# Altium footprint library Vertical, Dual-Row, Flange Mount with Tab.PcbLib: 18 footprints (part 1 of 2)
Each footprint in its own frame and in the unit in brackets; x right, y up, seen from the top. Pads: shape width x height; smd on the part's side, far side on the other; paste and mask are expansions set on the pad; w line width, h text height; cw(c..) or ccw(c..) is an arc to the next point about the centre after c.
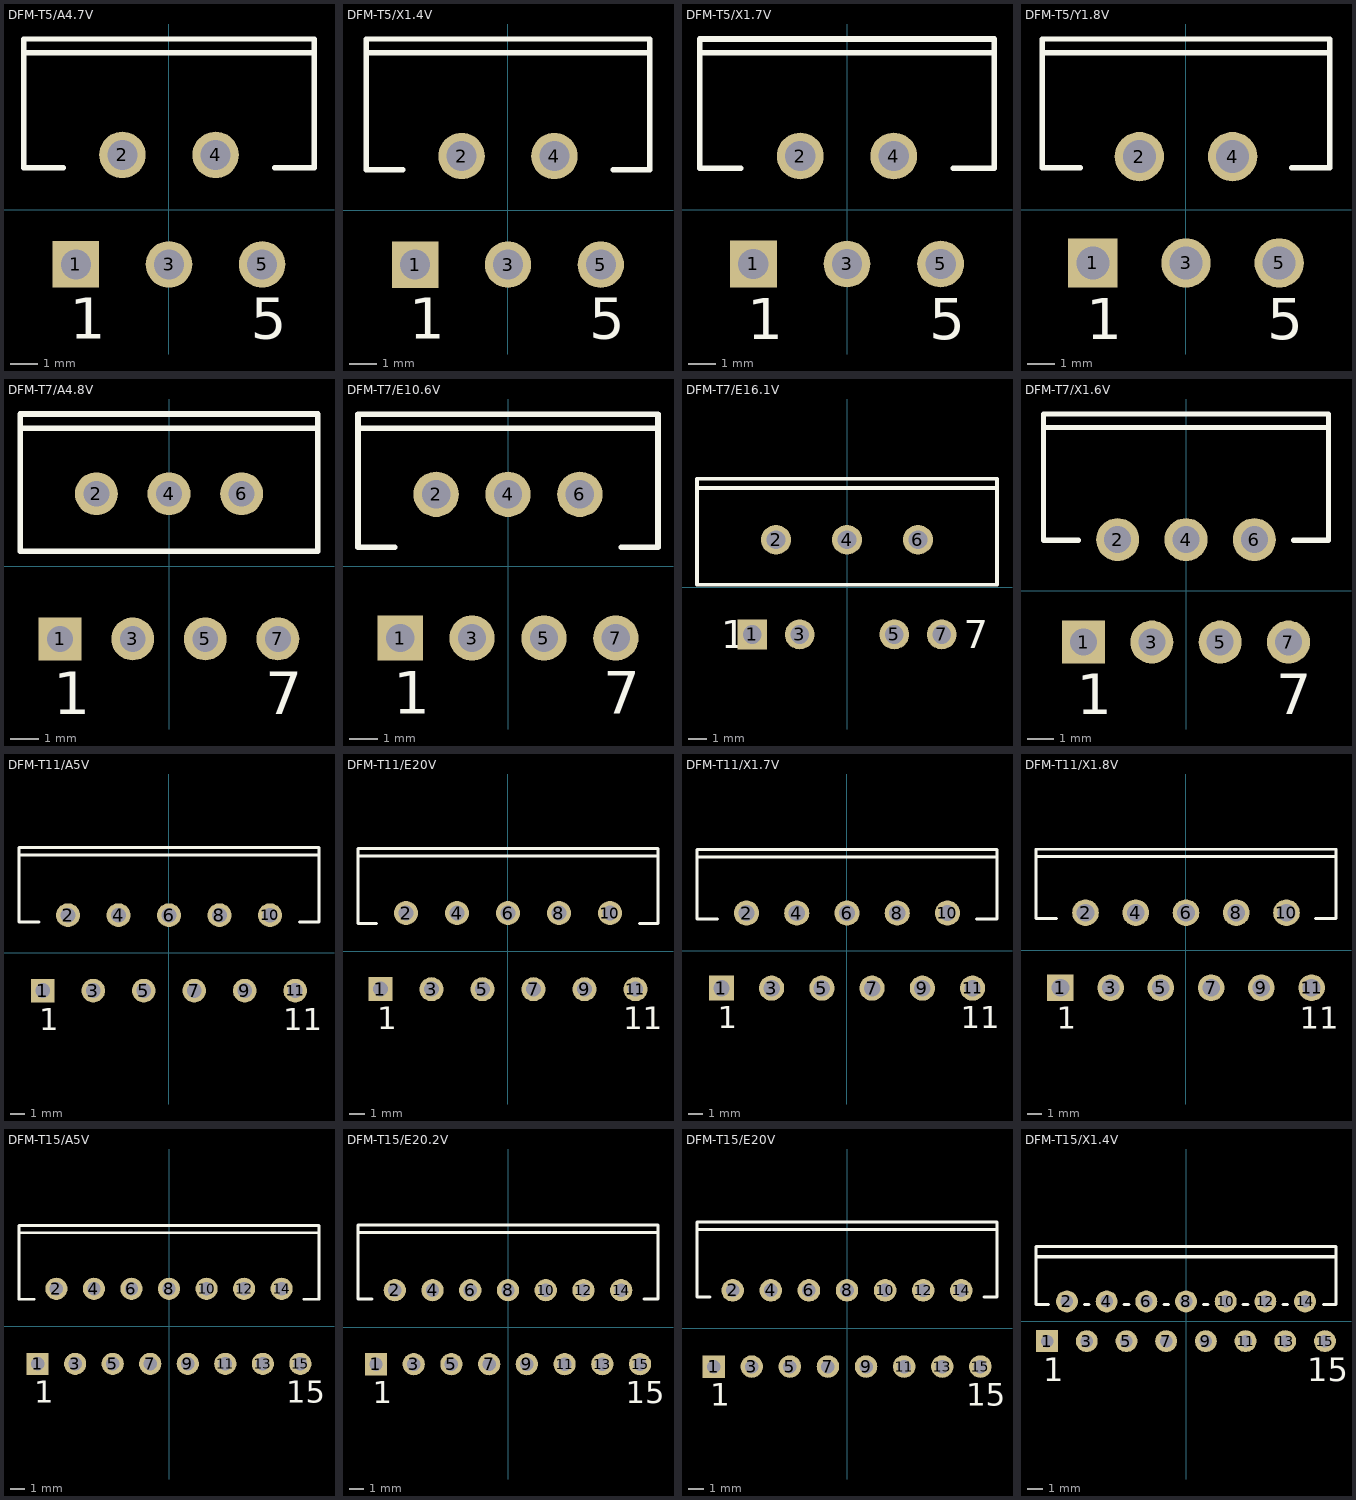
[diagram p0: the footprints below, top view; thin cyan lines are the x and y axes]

## DFM-T5/A4.7V [mm]
pads (5):
  rect 1.7x1.7 hole 1.1: 1(-3.4,-2)
  round 1.7 hole 1.1: 2(-1.7,2) 3(0,-2) 4(1.7,2) 5(3.4,-2)
Top Overlay:
  lines w0.2: -5.3,5.73 5.3,5.73 ; -3.854,1.53 -5.3,1.53 -5.3,6.23 5.3,6.23 5.3,1.53 3.854,1.53
  text "5" at 2.98,-4.725 h1.5
  text "1" at -3.62,-4.725 h1.5

## DFM-T5/X1.4V [mm]
pads (5):
  rect 1.7x1.7 hole 1.1: 1(-3.4,-1.99)
  round 1.7 hole 1.1: 2(-1.7,1.99) 3(0,-1.99) 4(1.7,1.99) 5(3.4,-1.99)
Top Overlay:
  lines w0.2: -5.2,5.78 5.2,5.78 ; -3.854,1.48 -5.2,1.48 -5.2,6.28 5.2,6.28 5.2,1.48 3.854,1.48
  text "1" at -3.62,-4.715 h1.5
  text "5" at 2.98,-4.715 h1.5

## DFM-T5/X1.7V [mm]
pads (5):
  rect 1.7x1.7 hole 1.1: 1(-3.4,-1.96)
  round 1.7 hole 1.1: 2(-1.7,1.96) 3(0,-1.96) 4(1.7,1.96) 5(3.4,-1.96)
Top Overlay:
  lines w0.2: -5.35,5.71 5.35,5.71 ; -3.854,1.51 -5.35,1.51 -5.35,6.21 5.35,6.21 5.35,1.51 3.854,1.51
  text "5" at 2.98,-4.685 h1.5
  text "1" at -3.62,-4.685 h1.5

## DFM-T5/Y1.8V [mm]
pads (5):
  rect 1.8x1.8 hole 1.2: 1(-3.4,-1.94)
  round 1.8 hole 1.2: 2(-1.7,1.94) 3(0,-1.94) 4(1.7,1.94) 5(3.4,-1.94)
Top Overlay:
  lines w0.2: -5.25,5.73 5.25,5.73 ; -3.854,1.53 -5.25,1.53 -5.25,6.23 5.25,6.23 5.25,1.53 3.854,1.53
  text "1" at -3.64,-4.715 h1.5
  text "5" at 2.96,-4.715 h1.5

## DFM-T7/A4.8V [mm]
pads (7):
  rect 1.5x1.5 hole 0.9: 1(-3.81,-2.54)
  round 1.5 hole 0.9: 2(-2.54,2.54) 3(-1.27,-2.54) 4(0,2.54) 5(1.27,-2.54) 6(2.54,2.54) 7(3.81,-2.54)
Top Overlay:
  lines w0.2: -5.2,4.83 5.2,4.83 ; -5.2,0.53 -5.2,5.33 5.2,5.33 5.2,0.53 -5.2,0.53
  text "1" at -4.05,-5.165 h1.5
  text "7" at 3.37,-5.165 h1.5

## DFM-T7/E10.6V [mm]
pads (7):
  rect 1.6x1.6 hole 1: 1(-3.81,-2.54)
  round 1.6 hole 1: 2(-2.54,2.54) 3(-1.27,-2.54) 4(0,2.54) 5(1.27,-2.54) 6(2.54,2.54) 7(3.81,-2.54)
Top Overlay:
  lines w0.2: -5.3,4.87 5.3,4.87 ; -4,0.67 -5.3,0.67 -5.3,5.37 5.3,5.37 5.3,0.67 4,0.67
  text "1" at -4.06,-5.215 h1.5
  text "7" at 3.36,-5.215 h1.5

## DFM-T7/E16.1V [mm]
pads (7):
  rect 1.6x1.6 hole 1: 1(-5.08,-2.54)
  round 1.6 hole 1: 2(-3.81,2.54) 3(-2.54,-2.54) 4(0,2.54) 5(2.54,-2.54) 6(3.81,2.54) 7(5.08,-2.54)
Top Overlay:
  lines w0.2: -8.05,5.32 8.05,5.32 ; -8.05,0.12 8.05,0.12 8.05,5.82 -8.05,5.82 -8.05,0.12
  text "7" at 6.255,-3.29 h1.5
  text "1" at -6.755,-3.29 h1.5

## DFM-T7/X1.6V [mm]
pads (7):
  rect 1.6x1.6 hole 1: 1(-3.81,-1.905)
  round 1.6 hole 1: 2(-2.54,1.905) 3(-1.27,-1.905) 4(0,1.905) 5(1.27,-1.905) 6(2.54,1.905) 7(3.81,-1.905)
Top Overlay:
  lines w0.2: -5.3,6.075 5.3,6.075 ; -4,1.875 -5.3,1.875 -5.3,6.575 5.3,6.575 5.3,1.875 4,1.875
  text "1" at -4.06,-4.58 h1.5
  text "7" at 3.36,-4.58 h1.5

## DFM-T11/A5V [mm]
pads (11):
  rect 1.6x1.6 hole 1: 1(-8.5,-2.54)
  round 1.6 hole 1: 2(-6.8,2.54) 3(-5.1,-2.54) 4(-3.4,2.54) 5(-1.7,-2.54) 6(0,2.54) 7(1.7,-2.54) 8(3.4,2.54) 9(5.1,-2.54) 10(6.8,2.54) 11(8.5,-2.54)
Top Overlay:
  lines w0.2: -10.1,6.59 10.1,6.59 ; -8.754,2.09 -10.1,2.09 -10.1,7.09 10.1,7.09 10.1,2.09 8.774,2.09
  text "11" at 7.69,-5.215 h1.5
  text "1" at -8.73,-5.215 h1.5

## DFM-T11/E20V [mm]
pads (11):
  rect 1.6x1.6 hole 1: 1(-8.5,-2.54)
  round 1.6 hole 1: 2(-6.8,2.54) 3(-5.1,-2.54) 4(-3.4,2.54) 5(-1.7,-2.54) 6(0,2.54) 7(1.7,-2.54) 8(3.4,2.54) 9(5.1,-2.54) 10(6.8,2.54) 11(8.5,-2.54)
Top Overlay:
  lines w0.2: -10,6.33 9.9,6.33 ; -8.754,1.83 -10,1.83 -10,6.83 10,6.83 10,1.83 8.774,1.83
  text "1" at -8.73,-5.215 h1.5
  text "11" at 7.67,-5.215 h1.5

## DFM-T11/X1.7V [mm]
pads (11):
  rect 1.7x1.7 hole 1.1: 1(-8.5,-2.54)
  round 1.7 hole 1.1: 2(-6.8,2.54) 3(-5.1,-2.54) 4(-3.4,2.54) 5(-1.7,-2.54) 6(0,2.54) 7(1.7,-2.54) 8(3.4,2.54) 9(5.1,-2.54) 10(6.8,2.54) 11(8.5,-2.54)
Top Overlay:
  lines w0.2: -10.15,6.34 10.15,6.34 ; -8.754,2.14 -10.15,2.14 -10.15,6.84 10.15,6.84 10.15,2.14 8.774,2.14
  text "11" at 7.71,-5.265 h1.5
  text "1" at -8.74,-5.265 h1.5

## DFM-T11/X1.8V [mm]
pads (11):
  rect 1.8x1.8 hole 1.2: 1(-8.5,-2.54)
  round 1.8 hole 1.2: 2(-6.8,2.54) 3(-5.1,-2.54) 4(-3.4,2.54) 5(-1.7,-2.54) 6(0,2.54) 7(1.7,-2.54) 8(3.4,2.54) 9(5.1,-2.54) 10(6.8,2.54) 11(8.5,-2.54)
Top Overlay:
  lines w0.2: -10.15,6.33 10.15,6.33 ; -8.754,2.13 -10.15,2.13 -10.15,6.83 10.15,6.83 10.15,2.13 8.774,2.13
  text "11" at 7.71,-5.315 h1.5
  text "1" at -8.74,-5.315 h1.5

## DFM-T15/A5V [mm]
pads (15):
  rect 1.5x1.5 hole 0.9: 1(-8.89,-2.54)
  round 1.5 hole 0.9: 2(-7.62,2.54) 3(-6.35,-2.54) 4(-5.08,2.54) 5(-3.81,-2.54) 6(-2.54,2.54) 7(-1.27,-2.54) 8(0,2.54) 9(1.27,-2.54) 10(2.54,2.54) 11(3.81,-2.54) 12(5.08,2.54) 13(6.35,-2.54) 14(7.62,2.54) 15(8.89,-2.54)
Top Overlay:
  lines w0.2: -10.15,6.33 10.05,6.33 ; -9.144,1.83 -10.15,1.83 -10.15,6.83 10.15,6.83 10.15,1.83 9.144,1.83
  text "1" at -9.12,-5.165 h1.5
  text "15" at 7.95,-5.165 h1.5

## DFM-T15/E20.2V [mm]
pads (15):
  rect 1.5x1.5 hole 0.9: 1(-8.89,-2.49)
  round 1.5 hole 0.9: 2(-7.62,2.49) 3(-6.35,-2.49) 4(-5.08,2.49) 5(-3.81,-2.49) 6(-2.54,2.49) 7(-1.27,-2.49) 8(0,2.49) 9(1.27,-2.49) 10(2.54,2.49) 11(3.81,-2.49) 12(5.08,2.49) 13(6.35,-2.49) 14(7.62,2.49) 15(8.89,-2.49)
Top Overlay:
  lines w0.2: -10.1,6.39 10.1,6.39 ; -9.144,1.89 -10.1,1.89 -10.1,6.89 10.1,6.89 10.1,1.89 9.144,1.89
  text "15" at 7.94,-5.115 h1.5
  text "1" at -9.12,-5.115 h1.5

## DFM-T15/E20V [mm]
pads (15):
  rect 1.5x1.5 hole 0.9: 1(-8.89,-2.54)
  round 1.5 hole 0.9: 2(-7.62,2.54) 3(-6.35,-2.54) 4(-5.08,2.54) 5(-3.81,-2.54) 6(-2.54,2.54) 7(-1.27,-2.54) 8(0,2.54) 9(1.27,-2.54) 10(2.54,2.54) 11(3.81,-2.54) 12(5.08,2.54) 13(6.35,-2.54) 14(7.62,2.54) 15(8.89,-2.54)
Top Overlay:
  lines w0.2: -10,6.59 10,6.59 ; -9.144,2.09 -10,2.09 -10,7.09 10,7.09 10,2.09 9.144,2.09
  text "1" at -9.12,-5.165 h1.5
  text "15" at 7.94,-5.165 h1.5

## DFM-T15/X1.4V [mm]
pads (15):
  rect 1.4x1.4 hole 0.8: 1(-8.89,-1.27)
  round 1.4 hole 0.8: 2(-7.62,1.27) 3(-6.35,-1.27) 4(-5.08,1.27) 5(-3.81,-1.27) 6(-2.54,1.27) 7(-1.27,-1.27) 8(0,1.27) 9(1.27,-1.27) 10(2.54,1.27) 11(3.81,-1.27) 12(5.08,1.27) 13(6.35,-1.27) 14(7.62,1.27) 15(8.89,-1.27)
Top Overlay:
  lines w0.2: -9.6,4.13 9.6,4.13 ; -8.8,1.08 -9.6,1.08 -9.6,4.78 9.6,4.78 9.6,1.08 8.8,1.08 ; -6.5,1.08 -6.2,1.08 ; -3.96,1.08 -3.66,1.08 ; -1.42,1.08 -1.12,1.08 ; 1.12,1.08 1.42,1.08 ; 3.66,1.08 3.96,1.08 ; 6.2,1.08 6.5,1.08
  text "1" at -9.14,-3.845 h1.5
  text "15" at 7.765,-3.845 h1.5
